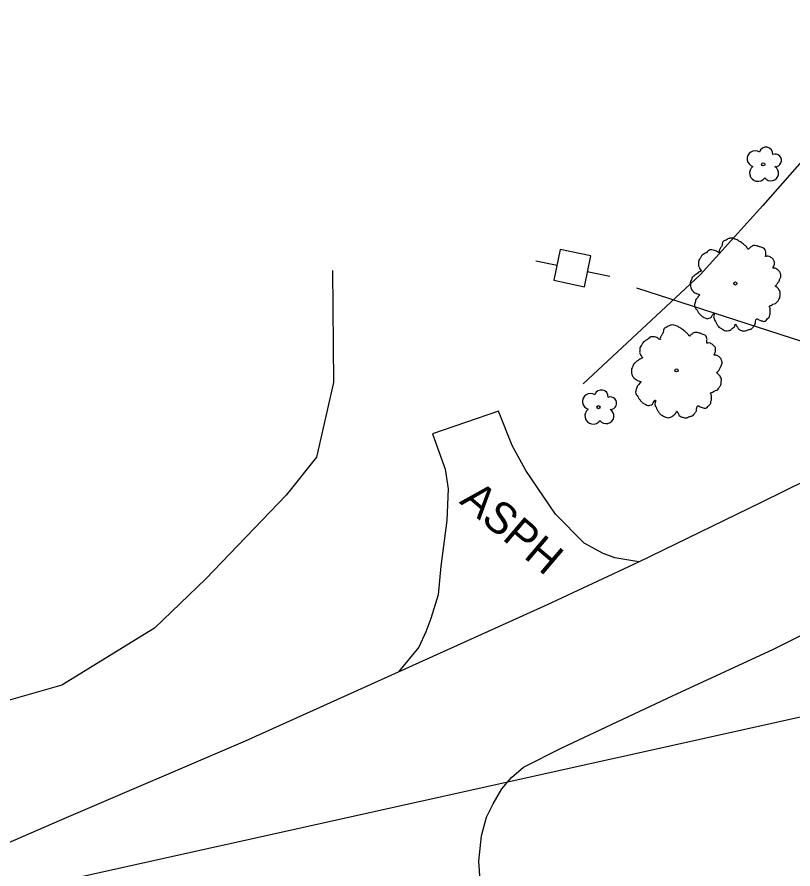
# Model space of a CAD drawing. Extents: x 2076109 to 2080761, y 592812 to 596750.
# Drawn here: x 2076714.3 to 2076837.6, y 595468.6 to 595604.1 of the extents above; entities that cross this region are included whole.
import ezdxf

# ---------------------------------------------------------------- set-up
doc = ezdxf.new("R2010")
doc.units = 0
for name, color, linetype in [('RD_EX_Driveway', 7, 'Continuous'), ('RD_EX_Driveway_txCode', 7, 'Continuous'), ('RD_EX_H2O', 7, 'Continuous'), ('RD_EX_Road', 7, 'Continuous'), ('RD_EX_UT', 7, 'Continuous'), ('RD_EX_VEG', 7, 'Continuous')]:
    doc.layers.add(name, color=color, linetype=linetype)

msp = doc.modelspace()

# ---------------------------------------------------------------- linework, layer by layer
at = {"layer": 'RD_EX_Driveway'}
msp.add_lwpolyline([(2076813.13, 595517.44), (2076809.31, 595518.07), (2076807.46, 595518.76), (2076804.44, 595520.41), (2076799.92, 595525.03), (2076795.17, 595531.98), (2076793.01, 595535.94), (2076790.82, 595541.4), (2076780.32, 595537.83), (2076782.37, 595532.21), (2076782.82, 595529.06), (2076782.61, 595524.03), (2076781.68, 595516.75), (2076781.24, 595512.23), (2076780.08, 595508.42), (2076779.26, 595506.31), (2076778.18, 595503.86), (2076774.96, 595499.94)], dxfattribs=at)
msp.add_lwpolyline([(2076813.13, 595517.44), (2076809.31, 595518.07), (2076807.46, 595518.76), (2076804.44, 595520.41), (2076799.92, 595525.03), (2076795.17, 595531.98), (2076793.01, 595535.94), (2076790.82, 595541.4), (2076780.32, 595537.83), (2076782.37, 595532.21), (2076782.82, 595529.06), (2076782.61, 595524.03), (2076781.68, 595516.75), (2076781.24, 595512.23), (2076780.08, 595508.42), (2076779.26, 595506.31), (2076778.18, 595503.86), (2076774.96, 595499.94)], dxfattribs=at)
at = {"layer": 'RD_EX_H2O'}
msp.add_lwpolyline([(2076953.18, 595787.61), (2076953.11, 595768.11), (2076952.56, 595756.13), (2076952.64, 595748.41), (2076952.76, 595745.08), (2076953.8, 595742.99), (2076953.36, 595730.22), (2076953.03, 595725.71), (2076951.39, 595721.38), (2076949.37, 595718.3), (2076942.5, 595711.04), (2076932.67, 595698.19), (2076918.85, 595680.89), (2076905.91, 595664.86), (2076891.97, 595647.71), (2076883.67, 595637.84), (2076877.03, 595627.21), (2076865.95, 595614.44), (2076853.87, 595600.18), (2076844.92, 595587.87), (2076832.87, 595574.13), (2076822.92, 595563.08), (2076804.28, 595545.77)], dxfattribs=at)
msp.add_lwpolyline([(2076953.18, 595787.61), (2076953.11, 595768.11), (2076952.56, 595756.13), (2076952.64, 595748.41), (2076952.76, 595745.08), (2076953.8, 595742.99), (2076953.36, 595730.22), (2076953.03, 595725.71), (2076951.39, 595721.38), (2076949.37, 595718.3), (2076942.5, 595711.04), (2076932.67, 595698.19), (2076918.85, 595680.89), (2076905.91, 595664.86), (2076891.97, 595647.71), (2076883.67, 595637.84), (2076877.03, 595627.21), (2076865.95, 595614.44), (2076853.87, 595600.18), (2076844.92, 595587.87), (2076832.87, 595574.13), (2076822.92, 595563.08), (2076804.28, 595545.77)], dxfattribs=at)
at = {"layer": 'RD_EX_Road'}
for points in [[(2076707.59, 595470.49), (2076721.43, 595476.47), (2076750.6, 595488.97), (2076774.96, 595499.94), (2076798.62, 595510.68), (2076813.13, 595517.44), (2076832.67, 595526.92), (2076854.37, 595537.63), (2076875.76, 595548.58), (2076901.14, 595561.82), (2076919.96, 595571.87), (2076946.71, 595586.58), (2076970.23, 595599.97)], [(2076707.59, 595470.49), (2076721.43, 595476.47), (2076750.6, 595488.97), (2076774.96, 595499.94), (2076798.62, 595510.68), (2076813.13, 595517.44), (2076832.67, 595526.92), (2076854.37, 595537.63), (2076875.76, 595548.58), (2076901.14, 595561.82), (2076919.96, 595571.87), (2076946.71, 595586.58), (2076970.23, 595599.97)], [(2076787.98, 595465.96), (2076787.69, 595469.85), (2076788.12, 595473.87), (2076788.92, 595476.83), (2076790, 595478.96), (2076791.35, 595481.36), (2076792.92, 595483.16), (2076794.83, 595484.81), (2076800.92, 595487.89), (2076818.52, 595496.12), (2076834.57, 595503.55), (2076852.99, 595512.75), (2076872.44, 595522.55), (2076895.16, 595534.41), (2076918.14, 595547.06), (2076946.45, 595562.46), (2076964.21, 595572.12)], [(2076787.98, 595465.96), (2076787.69, 595469.85), (2076788.12, 595473.87), (2076788.92, 595476.83), (2076790, 595478.96), (2076791.35, 595481.36), (2076792.92, 595483.16), (2076794.83, 595484.81), (2076800.92, 595487.89), (2076818.52, 595496.12), (2076834.57, 595503.55), (2076852.99, 595512.75), (2076872.44, 595522.55), (2076895.16, 595534.41), (2076918.14, 595547.06), (2076946.45, 595562.46), (2076964.21, 595572.12)]]:
    msp.add_lwpolyline(points, dxfattribs=at)
at = {"layer": 'RD_EX_UT'}
for p, q in [((2076800.64, 595567.13), (2076799.62, 595562.23)), ((2076800.64, 595567.13), (2076799.62, 595562.23)), ((2076805.54, 595566.11), (2076800.64, 595567.13)), ((2076805.54, 595566.11), (2076800.64, 595567.13)), ((2076796.76, 595565.32), (2076800.16, 595564.61)), ((2076796.76, 595565.32), (2076800.16, 595564.61)), ((2076804.51, 595561.21), (2076805.54, 595566.11)), ((2076804.51, 595561.21), (2076805.54, 595566.11)), ((2076804.94, 595563.61), (2076808.51, 595562.87)), ((2076804.94, 595563.61), (2076808.51, 595562.87)), ((2076799.62, 595562.23), (2076804.51, 595561.21)), ((2076799.62, 595562.23), (2076804.51, 595561.21)), ((2076812.76, 595561.03), (2076939.97, 595519.83)), ((2076812.76, 595561.03), (2076939.97, 595519.83)), ((2076566.44, 595432.36), (2076937.84, 595514.77)), ((2076566.44, 595432.36), (2076937.84, 595514.77))]:
    msp.add_line(p, q, dxfattribs=at)
at = {"layer": 'RD_EX_VEG'}
msp.add_lwpolyline([(2076764.43, 595563.77), (2076764.6, 595546), (2076761.88, 595534.12), (2076757.09, 595528.05), (2076744.3, 595514.75), (2076736.16, 595506.91), (2076721.44, 595497.84), (2076686.85, 595487.97)], dxfattribs=at)
msp.add_lwpolyline([(2076764.43, 595563.77), (2076764.6, 595546), (2076761.88, 595534.12), (2076757.09, 595528.05), (2076744.3, 595514.75), (2076736.16, 595506.91), (2076721.44, 595497.84), (2076686.85, 595487.97)], dxfattribs=at)
for centre, radius in [((2076832.92, 595580.67), 0.25), ((2076832.92, 595580.67), 0.25), ((2076828.49, 595561.72), 0.25), ((2076828.49, 595561.72), 0.25), ((2076828.47, 595561.71), 0.0001), ((2076828.47, 595561.71), 0.0001), ((2076819.14, 595547.9), 0.25), ((2076819.14, 595547.9), 0.25), ((2076819.12, 595547.89), 0.0001), ((2076819.12, 595547.89), 0.0001), ((2076806.73, 595542.06), 0.25), ((2076806.73, 595542.06), 0.25)]:
    msp.add_circle(centre, radius, dxfattribs=at)
for centre, radius, start, end in [((2076831.63, 595581.56), 1.26, 56.0792, 254.3614), ((2076831.63, 595581.56), 1.26, 56.0792, 254.3614), ((2076833.37, 595582.32), 1.08, 354.6037, 164.3834), ((2076833.37, 595582.32), 1.08, 354.6037, 164.3834), ((2076834.82, 595581.29), 0.995, 268.39, 111.6741), ((2076834.82, 595581.29), 0.995, 268.39, 111.6741), ((2076832.07, 595579.29), 1.32, 126.51, 325.3863), ((2076832.07, 595579.29), 1.32, 126.51, 325.3863), ((2076834.14, 595579.27), 1.22, 216.1941, 57.732), ((2076834.14, 595579.27), 1.22, 216.1941, 57.732), ((2076805.44, 595542.95), 1.26, 56.0792, 254.3614), ((2076805.44, 595542.95), 1.26, 56.0792, 254.3614), ((2076807.19, 595543.71), 1.08, 354.6037, 164.3834), ((2076807.19, 595543.71), 1.08, 354.6037, 164.3834), ((2076808.63, 595542.68), 0.995, 268.39, 111.6741), ((2076808.63, 595542.68), 0.995, 268.39, 111.6741), ((2076805.89, 595540.68), 1.32, 126.51, 325.3863), ((2076805.89, 595540.68), 1.32, 126.51, 325.3863), ((2076807.95, 595540.66), 1.22, 216.1941, 57.732), ((2076807.95, 595540.66), 1.22, 216.1941, 57.732)]:
    msp.add_arc(centre, radius, start, end, dxfattribs=at)
for points in [[(2076833.23, 595567.09), (2076833.02, 595567.31), (2076832.71, 595567.44), (2076832.46, 595567.53), (2076832.24, 595567.61), (2076832, 595567.68), (2076831.66, 595567.74), (2076831.36, 595567.74), (2076831.1, 595567.63), (2076830.92, 595567.49), (2076830.7, 595567.31), (2076830.59, 595567.18), (2076830.47, 595567.24), (2076830.38, 595567.36), (2076830.24, 595567.58), (2076830.04, 595567.74), (2076829.85, 595567.9), (2076829.57, 595568.11), (2076829.31, 595568.33), (2076829.06, 595568.47), (2076828.78, 595568.65), (2076828.42, 595568.79), (2076828.07, 595568.93), (2076827.68, 595568.93), (2076827.18, 595568.73), (2076826.86, 595568.54), (2076826.58, 595568.45), (2076826.41, 595568.01), (2076826.31, 595567.63), (2076826.2, 595567.46), (2076825.98, 595567.09), (2076825.91, 595566.85), (2076825.88, 595566.62), (2076825.81, 595566.65), (2076825.49, 595566.86), (2076825.2, 595566.97), (2076824.73, 595567.08), (2076824.41, 595567.05), (2076824.12, 595566.87), (2076823.88, 595566.62), (2076823.67, 595566.53), (2076823.44, 595566.37), (2076823.37, 595566.33), (2076823.12, 595566.11), (2076822.91, 595565.71), (2076822.7, 595565.42), (2076822.65, 595565.17), (2076822.65, 595564.94), (2076822.62, 595564.64), (2076822.78, 595564.21), (2076822.96, 595563.92), (2076823.1, 595563.77), (2076822.64, 595563.5), (2076822.38, 595563.27), (2076822.02, 595563.05), (2076821.97, 595562.99), (2076821.63, 595562.66), (2076821.53, 595562.32), (2076821.35, 595561.98), (2076821.33, 595561.7), (2076821.35, 595561.29), (2076821.45, 595560.91), (2076821.75, 595560.49), (2076822.07, 595560.25), (2076822.62, 595560.01), (2076822.86, 595559.91), (2076822.73, 595559.79), (2076822.5, 595559.49), (2076822.23, 595559.16), (2076822.13, 595558.82), (2076822.03, 595558.54), (2076821.98, 595558.26), (2076822.09, 595557.88), (2076822.34, 595557.56), (2076822.57, 595557.17), (2076822.86, 595556.82), (2076823.23, 595556.48), (2076823.78, 595556.2), (2076824.07, 595556.12), (2076824.26, 595556.19), (2076824.66, 595556.35), (2076824.76, 595556.55), (2076825.17, 595556.99), (2076825.13, 595556.79), (2076825.04, 595556.41), (2076825.23, 595555.86), (2076825.42, 595555.47), (2076825.68, 595555.05), (2076825.86, 595554.8), (2076826.27, 595554.54), (2076826.61, 595554.36), (2076826.97, 595554.21), (2076827.38, 595554.23), (2076827.69, 595554.32), (2076827.91, 595554.5), (2076828.21, 595554.74), (2076828.36, 595554.84)], [(2076833.23, 595567.09), (2076833.02, 595567.31), (2076832.71, 595567.44), (2076832.46, 595567.53), (2076832.24, 595567.61), (2076832, 595567.68), (2076831.66, 595567.74), (2076831.36, 595567.74), (2076831.1, 595567.63), (2076830.92, 595567.49), (2076830.7, 595567.31), (2076830.59, 595567.18), (2076830.47, 595567.24), (2076830.38, 595567.36), (2076830.24, 595567.58), (2076830.04, 595567.74), (2076829.85, 595567.9), (2076829.57, 595568.11), (2076829.31, 595568.33), (2076829.06, 595568.47), (2076828.78, 595568.65), (2076828.42, 595568.79), (2076828.07, 595568.93), (2076827.68, 595568.93), (2076827.18, 595568.73), (2076826.86, 595568.54), (2076826.58, 595568.45), (2076826.41, 595568.01), (2076826.31, 595567.63), (2076826.2, 595567.46), (2076825.98, 595567.09), (2076825.91, 595566.85), (2076825.88, 595566.62), (2076825.81, 595566.65), (2076825.49, 595566.86), (2076825.2, 595566.97), (2076824.73, 595567.08), (2076824.41, 595567.05), (2076824.12, 595566.87), (2076823.88, 595566.62), (2076823.67, 595566.53), (2076823.44, 595566.37), (2076823.37, 595566.33), (2076823.12, 595566.11), (2076822.91, 595565.71), (2076822.7, 595565.42), (2076822.65, 595565.17), (2076822.65, 595564.94), (2076822.62, 595564.64), (2076822.78, 595564.21), (2076822.96, 595563.92), (2076823.1, 595563.77), (2076822.64, 595563.5), (2076822.38, 595563.27), (2076822.02, 595563.05), (2076821.97, 595562.99), (2076821.63, 595562.66), (2076821.53, 595562.32), (2076821.35, 595561.98), (2076821.33, 595561.7), (2076821.35, 595561.29), (2076821.45, 595560.91), (2076821.75, 595560.49), (2076822.07, 595560.25), (2076822.62, 595560.01), (2076822.86, 595559.91), (2076822.73, 595559.79), (2076822.5, 595559.49), (2076822.23, 595559.16), (2076822.13, 595558.82), (2076822.03, 595558.54), (2076821.98, 595558.26), (2076822.09, 595557.88), (2076822.34, 595557.56), (2076822.57, 595557.17), (2076822.86, 595556.82), (2076823.23, 595556.48), (2076823.78, 595556.2), (2076824.07, 595556.12), (2076824.26, 595556.19), (2076824.66, 595556.35), (2076824.76, 595556.55), (2076825.17, 595556.99), (2076825.13, 595556.79), (2076825.04, 595556.41), (2076825.23, 595555.86), (2076825.42, 595555.47), (2076825.68, 595555.05), (2076825.86, 595554.8), (2076826.27, 595554.54), (2076826.61, 595554.36), (2076826.97, 595554.21), (2076827.38, 595554.23), (2076827.69, 595554.32), (2076827.91, 595554.5), (2076828.21, 595554.74), (2076828.36, 595554.84)], [(2076828.36, 595554.84), (2076828.42, 595555.02), (2076828.54, 595555.24), (2076828.58, 595555.17), (2076828.68, 595555.02), (2076828.81, 595554.75), (2076828.93, 595554.55), (2076829.2, 595554.36), (2076829.47, 595554.25), (2076829.99, 595554.17), (2076830.51, 595554.36), (2076830.98, 595554.48), (2076831.24, 595554.68), (2076831.35, 595554.88), (2076831.66, 595555.28), (2076831.67, 595555.6), (2076831.71, 595555.73), (2076831.89, 595556.1), (2076831.98, 595556.09), (2076832.22, 595555.95), (2076832.59, 595555.8), (2076832.88, 595555.72), (2076833.16, 595555.71), (2076833.37, 595555.83), (2076833.61, 595556.15), (2076833.9, 595556.42), (2076833.94, 595556.58), (2076833.96, 595556.76), (2076834.04, 595556.96), (2076834.02, 595557.18), (2076834.04, 595557.35), (2076834.03, 595557.49), (2076834.03, 595557.69), (2076833.98, 595557.9), (2076833.9, 595558.03), (2076833.96, 595558.18), (2076834.2, 595558.24), (2076834.3, 595558.28), (2076834.47, 595558.43), (2076834.87, 595558.56), (2076835.16, 595558.83), (2076835.4, 595559.18), (2076835.54, 595559.43), (2076835.6, 595559.73), (2076835.61, 595560.05), (2076835.63, 595560.27), (2076835.58, 595560.47), (2076835.41, 595560.78), (2076835.25, 595560.98), (2076834.99, 595561.21), (2076834.87, 595561.37), (2076834.92, 595561.4), (2076835.02, 595561.51), (2076835.19, 595561.72), (2076835.43, 595562.11), (2076835.64, 595562.59), (2076835.65, 595562.61), (2076835.74, 595562.86), (2076835.7, 595563.16), (2076835.63, 595563.35), (2076835.56, 595563.58), (2076835.38, 595563.76), (2076835.16, 595563.95), (2076834.91, 595564.09), (2076834.7, 595564.14), (2076834.48, 595564.16), (2076834.52, 595564.32), (2076834.64, 595564.62), (2076834.7, 595564.76), (2076834.7, 595564.99), (2076834.66, 595565.29), (2076834.39, 595565.68), (2076833.87, 595566.03), (2076833.51, 595566.07), (2076833.29, 595566.03), (2076833.33, 595566.16), (2076833.31, 595566.44), (2076833.34, 595566.64), (2076833.29, 595566.85), (2076833.24, 595567.02), (2076833.2, 595567.12)], [(2076828.36, 595554.84), (2076828.42, 595555.02), (2076828.54, 595555.24), (2076828.58, 595555.17), (2076828.68, 595555.02), (2076828.81, 595554.75), (2076828.93, 595554.55), (2076829.2, 595554.36), (2076829.47, 595554.25), (2076829.99, 595554.17), (2076830.51, 595554.36), (2076830.98, 595554.48), (2076831.24, 595554.68), (2076831.35, 595554.88), (2076831.66, 595555.28), (2076831.67, 595555.6), (2076831.71, 595555.73), (2076831.89, 595556.1), (2076831.98, 595556.09), (2076832.22, 595555.95), (2076832.59, 595555.8), (2076832.88, 595555.72), (2076833.16, 595555.71), (2076833.37, 595555.83), (2076833.61, 595556.15), (2076833.9, 595556.42), (2076833.94, 595556.58), (2076833.96, 595556.76), (2076834.04, 595556.96), (2076834.02, 595557.18), (2076834.04, 595557.35), (2076834.03, 595557.49), (2076834.03, 595557.69), (2076833.98, 595557.9), (2076833.9, 595558.03), (2076833.96, 595558.18), (2076834.2, 595558.24), (2076834.3, 595558.28), (2076834.47, 595558.43), (2076834.87, 595558.56), (2076835.16, 595558.83), (2076835.4, 595559.18), (2076835.54, 595559.43), (2076835.6, 595559.73), (2076835.61, 595560.05), (2076835.63, 595560.27), (2076835.58, 595560.47), (2076835.41, 595560.78), (2076835.25, 595560.98), (2076834.99, 595561.21), (2076834.87, 595561.37), (2076834.92, 595561.4), (2076835.02, 595561.51), (2076835.19, 595561.72), (2076835.43, 595562.11), (2076835.64, 595562.59), (2076835.65, 595562.61), (2076835.74, 595562.86), (2076835.7, 595563.16), (2076835.63, 595563.35), (2076835.56, 595563.58), (2076835.38, 595563.76), (2076835.16, 595563.95), (2076834.91, 595564.09), (2076834.7, 595564.14), (2076834.48, 595564.16), (2076834.52, 595564.32), (2076834.64, 595564.62), (2076834.7, 595564.76), (2076834.7, 595564.99), (2076834.66, 595565.29), (2076834.39, 595565.68), (2076833.87, 595566.03), (2076833.51, 595566.07), (2076833.29, 595566.03), (2076833.33, 595566.16), (2076833.31, 595566.44), (2076833.34, 595566.64), (2076833.29, 595566.85), (2076833.24, 595567.02), (2076833.2, 595567.12)], [(2076823.88, 595553.27), (2076823.67, 595553.49), (2076823.36, 595553.62), (2076823.1, 595553.71), (2076822.89, 595553.8), (2076822.65, 595553.87), (2076822.31, 595553.93), (2076822.01, 595553.92), (2076821.75, 595553.81), (2076821.57, 595553.67), (2076821.35, 595553.49), (2076821.24, 595553.36), (2076821.12, 595553.42), (2076821.03, 595553.54), (2076820.88, 595553.76), (2076820.69, 595553.92), (2076820.5, 595554.08), (2076820.22, 595554.29), (2076819.95, 595554.52), (2076819.71, 595554.66), (2076819.43, 595554.83), (2076819.07, 595554.98), (2076818.72, 595555.11), (2076818.33, 595555.11), (2076817.83, 595554.91), (2076817.51, 595554.73), (2076817.23, 595554.63), (2076817.06, 595554.19), (2076816.96, 595553.81), (2076816.85, 595553.65), (2076816.63, 595553.27), (2076816.56, 595553.04), (2076816.53, 595552.8), (2076816.46, 595552.83), (2076816.14, 595553.04), (2076815.85, 595553.16), (2076815.38, 595553.26), (2076815.06, 595553.23), (2076814.77, 595553.05), (2076814.53, 595552.8), (2076814.32, 595552.71), (2076814.09, 595552.55), (2076814.02, 595552.51), (2076813.77, 595552.3), (2076813.56, 595551.89), (2076813.35, 595551.61), (2076813.3, 595551.35), (2076813.3, 595551.12), (2076813.27, 595550.82), (2076813.43, 595550.39), (2076813.61, 595550.1), (2076813.75, 595549.95), (2076813.29, 595549.69), (2076813.03, 595549.45), (2076812.67, 595549.23), (2076812.62, 595549.17), (2076812.28, 595548.84), (2076812.18, 595548.5), (2076812, 595548.16), (2076811.98, 595547.88), (2076812, 595547.47), (2076812.1, 595547.09), (2076812.4, 595546.67), (2076812.72, 595546.43), (2076813.27, 595546.19), (2076813.51, 595546.09), (2076813.38, 595545.97), (2076813.15, 595545.67), (2076812.88, 595545.35), (2076812.78, 595545), (2076812.68, 595544.73), (2076812.63, 595544.44), (2076812.74, 595544.06), (2076812.99, 595543.74), (2076813.22, 595543.35), (2076813.51, 595543), (2076813.88, 595542.66), (2076814.43, 595542.39), (2076814.72, 595542.3), (2076814.91, 595542.37), (2076815.31, 595542.53), (2076815.41, 595542.73), (2076815.82, 595543.17), (2076815.78, 595542.98), (2076815.69, 595542.6), (2076815.88, 595542.04), (2076816.07, 595541.65), (2076816.33, 595541.23), (2076816.51, 595540.98), (2076816.92, 595540.73), (2076817.26, 595540.54), (2076817.62, 595540.39), (2076818.03, 595540.41), (2076818.34, 595540.51), (2076818.56, 595540.68), (2076818.86, 595540.92), (2076819.01, 595541.02)], [(2076823.88, 595553.27), (2076823.67, 595553.49), (2076823.36, 595553.62), (2076823.1, 595553.71), (2076822.89, 595553.8), (2076822.65, 595553.87), (2076822.31, 595553.93), (2076822.01, 595553.92), (2076821.75, 595553.81), (2076821.57, 595553.67), (2076821.35, 595553.49), (2076821.24, 595553.36), (2076821.12, 595553.42), (2076821.03, 595553.54), (2076820.88, 595553.76), (2076820.69, 595553.92), (2076820.5, 595554.08), (2076820.22, 595554.29), (2076819.95, 595554.52), (2076819.71, 595554.66), (2076819.43, 595554.83), (2076819.07, 595554.98), (2076818.72, 595555.11), (2076818.33, 595555.11), (2076817.83, 595554.91), (2076817.51, 595554.73), (2076817.23, 595554.63), (2076817.06, 595554.19), (2076816.96, 595553.81), (2076816.85, 595553.65), (2076816.63, 595553.27), (2076816.56, 595553.04), (2076816.53, 595552.8), (2076816.46, 595552.83), (2076816.14, 595553.04), (2076815.85, 595553.16), (2076815.38, 595553.26), (2076815.06, 595553.23), (2076814.77, 595553.05), (2076814.53, 595552.8), (2076814.32, 595552.71), (2076814.09, 595552.55), (2076814.02, 595552.51), (2076813.77, 595552.3), (2076813.56, 595551.89), (2076813.35, 595551.61), (2076813.3, 595551.35), (2076813.3, 595551.12), (2076813.27, 595550.82), (2076813.43, 595550.39), (2076813.61, 595550.1), (2076813.75, 595549.95), (2076813.29, 595549.69), (2076813.03, 595549.45), (2076812.67, 595549.23), (2076812.62, 595549.17), (2076812.28, 595548.84), (2076812.18, 595548.5), (2076812, 595548.16), (2076811.98, 595547.88), (2076812, 595547.47), (2076812.1, 595547.09), (2076812.4, 595546.67), (2076812.72, 595546.43), (2076813.27, 595546.19), (2076813.51, 595546.09), (2076813.38, 595545.97), (2076813.15, 595545.67), (2076812.88, 595545.35), (2076812.78, 595545), (2076812.68, 595544.73), (2076812.63, 595544.44), (2076812.74, 595544.06), (2076812.99, 595543.74), (2076813.22, 595543.35), (2076813.51, 595543), (2076813.88, 595542.66), (2076814.43, 595542.39), (2076814.72, 595542.3), (2076814.91, 595542.37), (2076815.31, 595542.53), (2076815.41, 595542.73), (2076815.82, 595543.17), (2076815.78, 595542.98), (2076815.69, 595542.6), (2076815.88, 595542.04), (2076816.07, 595541.65), (2076816.33, 595541.23), (2076816.51, 595540.98), (2076816.92, 595540.73), (2076817.26, 595540.54), (2076817.62, 595540.39), (2076818.03, 595540.41), (2076818.34, 595540.51), (2076818.56, 595540.68), (2076818.86, 595540.92), (2076819.01, 595541.02)], [(2076819.01, 595541.02), (2076819.06, 595541.2), (2076819.19, 595541.42), (2076819.23, 595541.36), (2076819.33, 595541.21), (2076819.46, 595540.93), (2076819.58, 595540.73), (2076819.85, 595540.54), (2076820.12, 595540.44), (2076820.64, 595540.35), (2076821.16, 595540.54), (2076821.63, 595540.66), (2076821.89, 595540.86), (2076822, 595541.07), (2076822.31, 595541.46), (2076822.31, 595541.78), (2076822.36, 595541.91), (2076822.54, 595542.28), (2076822.63, 595542.27), (2076822.87, 595542.13), (2076823.24, 595541.98), (2076823.53, 595541.9), (2076823.81, 595541.89), (2076824.02, 595542.01), (2076824.26, 595542.33), (2076824.55, 595542.6), (2076824.59, 595542.77), (2076824.61, 595542.95), (2076824.69, 595543.15), (2076824.67, 595543.36), (2076824.69, 595543.54), (2076824.68, 595543.68), (2076824.68, 595543.87), (2076824.63, 595544.08), (2076824.55, 595544.22), (2076824.61, 595544.36), (2076824.85, 595544.42), (2076824.95, 595544.46), (2076825.12, 595544.62), (2076825.52, 595544.74), (2076825.81, 595545.01), (2076826.05, 595545.37), (2076826.19, 595545.61), (2076826.25, 595545.91), (2076826.26, 595546.23), (2076826.28, 595546.45), (2076826.23, 595546.66), (2076826.06, 595546.96), (2076825.9, 595547.16), (2076825.64, 595547.39), (2076825.52, 595547.56), (2076825.57, 595547.58), (2076825.67, 595547.69), (2076825.84, 595547.9), (2076826.08, 595548.29), (2076826.29, 595548.77), (2076826.3, 595548.79), (2076826.39, 595549.05), (2076826.35, 595549.34), (2076826.28, 595549.53), (2076826.21, 595549.76), (2076826.03, 595549.94), (2076825.81, 595550.13), (2076825.56, 595550.27), (2076825.35, 595550.33), (2076825.13, 595550.34), (2076825.17, 595550.51), (2076825.29, 595550.8), (2076825.35, 595550.95), (2076825.35, 595551.18), (2076825.31, 595551.48), (2076825.04, 595551.86), (2076824.52, 595552.21), (2076824.16, 595552.25), (2076823.93, 595552.22), (2076823.98, 595552.34), (2076823.95, 595552.62), (2076823.99, 595552.82), (2076823.94, 595553.03), (2076823.89, 595553.2), (2076823.85, 595553.31)], [(2076819.01, 595541.02), (2076819.06, 595541.2), (2076819.19, 595541.42), (2076819.23, 595541.36), (2076819.33, 595541.21), (2076819.46, 595540.93), (2076819.58, 595540.73), (2076819.85, 595540.54), (2076820.12, 595540.44), (2076820.64, 595540.35), (2076821.16, 595540.54), (2076821.63, 595540.66), (2076821.89, 595540.86), (2076822, 595541.07), (2076822.31, 595541.46), (2076822.31, 595541.78), (2076822.36, 595541.91), (2076822.54, 595542.28), (2076822.63, 595542.27), (2076822.87, 595542.13), (2076823.24, 595541.98), (2076823.53, 595541.9), (2076823.81, 595541.89), (2076824.02, 595542.01), (2076824.26, 595542.33), (2076824.55, 595542.6), (2076824.59, 595542.77), (2076824.61, 595542.95), (2076824.69, 595543.15), (2076824.67, 595543.36), (2076824.69, 595543.54), (2076824.68, 595543.68), (2076824.68, 595543.87), (2076824.63, 595544.08), (2076824.55, 595544.22), (2076824.61, 595544.36), (2076824.85, 595544.42), (2076824.95, 595544.46), (2076825.12, 595544.62), (2076825.52, 595544.74), (2076825.81, 595545.01), (2076826.05, 595545.37), (2076826.19, 595545.61), (2076826.25, 595545.91), (2076826.26, 595546.23), (2076826.28, 595546.45), (2076826.23, 595546.66), (2076826.06, 595546.96), (2076825.9, 595547.16), (2076825.64, 595547.39), (2076825.52, 595547.56), (2076825.57, 595547.58), (2076825.67, 595547.69), (2076825.84, 595547.9), (2076826.08, 595548.29), (2076826.29, 595548.77), (2076826.3, 595548.79), (2076826.39, 595549.05), (2076826.35, 595549.34), (2076826.28, 595549.53), (2076826.21, 595549.76), (2076826.03, 595549.94), (2076825.81, 595550.13), (2076825.56, 595550.27), (2076825.35, 595550.33), (2076825.13, 595550.34), (2076825.17, 595550.51), (2076825.29, 595550.8), (2076825.35, 595550.95), (2076825.35, 595551.18), (2076825.31, 595551.48), (2076825.04, 595551.86), (2076824.52, 595552.21), (2076824.16, 595552.25), (2076823.93, 595552.22), (2076823.98, 595552.34), (2076823.95, 595552.62), (2076823.99, 595552.82), (2076823.94, 595553.03), (2076823.89, 595553.2), (2076823.85, 595553.31)]]:
    msp.add_spline(points, degree=3, dxfattribs=at)

# ---------------------------------------------------------------- texts
at = {"layer": 'RD_EX_Driveway_txCode'}
msp.add_text('ASPH', height=5, rotation=319.6274, dxfattribs=at).set_placement((2076784.49, 595526.89))
msp.add_text('ASPH', height=5, rotation=319.6274, dxfattribs=at).set_placement((2076784.49, 595526.89))

doc.saveas('drawing.dxf')
